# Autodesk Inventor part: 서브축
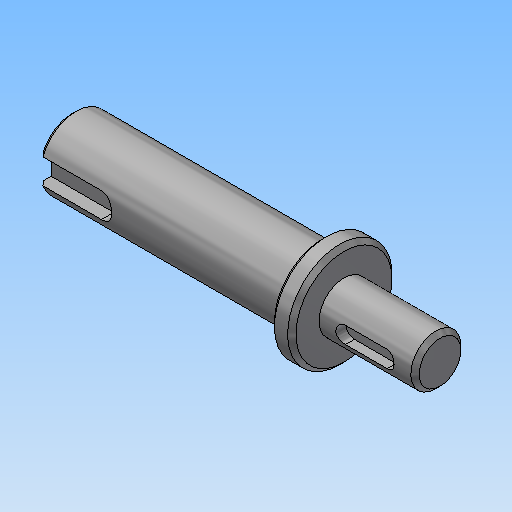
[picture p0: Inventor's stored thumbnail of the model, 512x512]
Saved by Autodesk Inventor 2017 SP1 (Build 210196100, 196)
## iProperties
Created: 2018-09
Part Number: 서브축
Document SubType Name: Modeling
Density: 1 g/cm^3
Material: 강철, 연강
Appearance: 강철
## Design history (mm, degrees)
sketch "스케치1"
  geometry: L1 (-18.818, -7)-(-18.818, 7) reference; L2 (-41.331, -13.5)-(-41.331, 13.5) reference; L3 (-46.5, 12.249)-(-46.5, -12.249) reference; L4 (-18.331, 0)-(-106.5, 0); L5 (-18.331, 0)-(-18.331, -6); L6 (-18.331, -6)-(-41.331, -6); L7 (-41.331, -12.5)-(-46.5, -12.5); L8 (-46.5, -8.5)-(-106.5, -8.5); L9 (-106.5, -8.5)-(-106.5, 0); L10 (-46.5, -8.5)-(-46.5, -12.5); L11 (-41.331, -6)-(-41.331, -12.5); 2 further points
  constraints: 17 end point, 5 point on line, 3 parallel, 3 perpendicular, 2 collinear, 1 midpoint
  dimensions: "d0" = 23 distance between parallel lines of L2 L5; "d1" = 12 diameter of L6 L4; "d2" = 25 diameter of L7 L4; "d3" = 17 diameter of L8 L4; "d4" = 60 distance of L8.start L8.end
revolve "회전1" sketch "스케치1" stored, may be unused: angle "d5" = 90 deg
chamfer "모따기1" distance "d6" = 1; stored, may be unused: second distance "d7" = 2, angle "d8" = 45 deg
node "작업 평면1"
sketch "스케치2"
  geometry: L1 (11.5, 5)-(11.5, -5) reference; L2 (-5.5, -2)-(4.5, -2); L3 (4.5, 2)-(-5.5, 2); A1 r 2 centre (4.5, 0) between (4.5, -2) and (4.5, 2); A2 r 2 centre (-5.5, 0) between (-5.5, 2) and (-5.5, -2); 2 further points
  constraints: 4 end point, 4 point on circle, 4 tangent, 2 centre point, 1 horizontal alignment, 1 midpoint, 1 parallel, 1 perpendicular
  dimensions: "d9" = 4 distance between parallel lines of L2 L3; "d10" = 14 dimension on A1 A2; "d11" = 5 distance edge to line of A1 L1
extrude "돌출1" cut sketch "스케치2" distance "d12" = 2.5; taper "d13" = 0 deg
node "작업 평면2"
sketch "스케치3"
  geometry: L1 (-30, -7.5)-(-30, 7.5) reference; L2 (-30, 3)-(-15, 3); L3 (-15, -3)-(-30, -3); A1 r 3 centre (-15, 0) between (-15, -3) and (-15, 3); 2 further points
  constraints: 4 end point, 2 perpendicular, 2 point on circle, 2 point on line, 2 tangent, 1 centre point, 1 horizontal alignment, 1 midpoint
  dimensions: "d14" = 6 distance between parallel lines of L3 L2; "d15" = 18 dimension on A1 L1
extrude "돌출2" cut sketch "스케치3" distance "d16" = 3.5; taper "d17" = 0 deg
node "솔리드1"
node "참조1"
node "참조2"
node "참조3"
